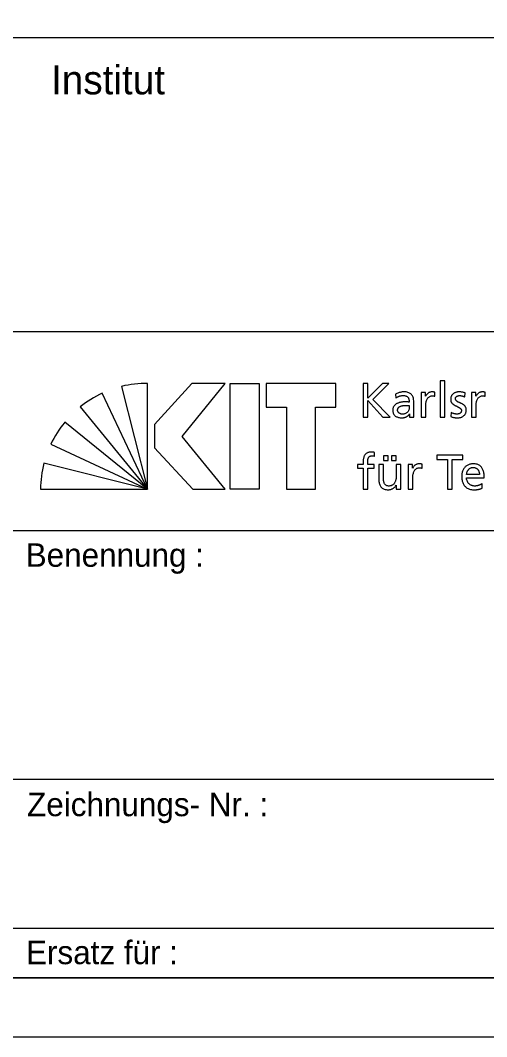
# Model space of a CAD drawing. Extents: x 0 to 21, y 0 to 14.9.
# Drawn here: x 18.816 to 19.808, y 0 to 2.162 of the extents above; entities that cross this region are included whole.
import ezdxf

# ---------------------------------------------------------------- set-up
doc = ezdxf.new("R2010")
doc.units = 0
doc.layers.add('90_Plankopf', color=7, linetype='Continuous')

msp = doc.modelspace()

# ---------------------------------------------------------------- linework, layer by layer
at = {"layer": '90_Plankopf'}
for p, q in [((20.9, 2.1248), (16.453, 2.1248)), ((16.453, 1.4998), (20.9, 1.4998)), ((16.453, 1.4998), (20.9, 1.4998)), ((19.087, 1.1647), (19.087, 1.3896)), ((19.5452, 1.3897), (19.5452, 1.3176)), ((19.087, 1.1647), (18.9908, 1.3688)), ((19.0319, 1.3833), (19.087, 1.1647)), ((19.6145, 1.3665), (19.615, 1.3583)), ((19.6982, 1.3621), (19.6982, 1.3708)), ((19.7614, 1.361), (19.7622, 1.3694)), ((19.8053, 1.3621), (19.8053, 1.3708)), ((19.6433, 1.3427), (19.6433, 1.3381)), ((19.653, 1.328), (19.653, 1.3497)), ((18.9436, 1.3396), (19.087, 1.1647)), ((19.7324, 1.328), (19.7319, 1.3193)), ((19.087, 1.1647), (18.9108, 1.3071)), ((19.5452, 1.3176), (19.5556, 1.3176)), ((19.5876, 1.3176), (19.6027, 1.3176)), ((18.881, 1.2603), (19.087, 1.1647)), ((19.5693, 1.2348), (19.5697, 1.2427)), ((19.087, 1.1647), (18.8664, 1.2197)), ((19.6707, 1.2091), (19.6707, 1.2178)), ((19.7927, 1.196), (19.7654, 1.196)), ((19.7654, 1.1888), (19.803, 1.1888)), ((19.7989, 1.1668), (19.7989, 1.1765)), ((18.8591, 1.1647), (19.087, 1.1647)), ((18.8, 1.0768), (20.9, 1.0768)), ((18.8, 0.548), (20.9, 0.548)), ((18.8, 0.2308), (20.9, 0.2308)), ((20.9, 0.125), (16.453, 0.125)), ((16.745, 0.125), (20.9, 0.125)), ((16.745, 0.125), (20.9, 0.125))]:
    msp.add_line(p, q, dxfattribs=at)
for points in [[(0, 0), (21.025, 0), (21.025, 14.85), (0, 14.85)], [(0.625, 14.725), (20.9, 14.725), (20.9, 0.125), (0.625, 0.125)], [(19.2517, 1.3897), (19.1809, 1.3897), (19.1018, 1.3025), (19.1018, 1.2523), (19.1834, 1.1647), (19.2521, 1.1647), (19.1606, 1.2766)], [(19.3243, 1.3897), (19.3243, 1.1647), (19.2625, 1.1647), (19.2625, 1.3897)], [(19.3391, 1.3897), (19.3391, 1.339), (19.3825, 1.339), (19.3825, 1.1647), (19.4443, 1.1647), (19.4443, 1.339), (19.4877, 1.339), (19.4877, 1.3897)]]:
    msp.add_lwpolyline(points, close=True, dxfattribs=at)
for points in [[(19.6027, 1.3176), (19.5662, 1.3556), (19.6, 1.3897), (19.5863, 1.3897), (19.5556, 1.358), (19.5556, 1.3897), (19.5452, 1.3897)], [(19.7095, 1.3176), (19.7192, 1.3176), (19.7192, 1.395), (19.7095, 1.395), (19.7095, 1.3176)], [(19.678, 1.3621), (19.6778, 1.3621), (19.6778, 1.3703), (19.6688, 1.3703), (19.6688, 1.3176), (19.6785, 1.3176), (19.6785, 1.3416)], [(19.7852, 1.3621), (19.785, 1.3621), (19.785, 1.3703), (19.7759, 1.3703), (19.7759, 1.3176), (19.7856, 1.3176), (19.7856, 1.3416)], [(19.5556, 1.3176), (19.5556, 1.3529), (19.5876, 1.3176)], [(19.6441, 1.3245), (19.6443, 1.3245), (19.6443, 1.3176), (19.6534, 1.3176)], [(19.5889, 1.2356), (19.5889, 1.2253), (19.5986, 1.2253), (19.5986, 1.2356), (19.5889, 1.2356)], [(19.6058, 1.2356), (19.6058, 1.2253), (19.6155, 1.2253), (19.6155, 1.2356), (19.6058, 1.2356)], [(19.7248, 1.1647), (19.7351, 1.1647), (19.7351, 1.2276), (19.7575, 1.2276), (19.7575, 1.2367), (19.7024, 1.2367), (19.7024, 1.2276), (19.7248, 1.2276), (19.7248, 1.1647)], [(19.5456, 1.2221), (19.5456, 1.2173), (19.5332, 1.2173), (19.5332, 1.2094), (19.5456, 1.2094), (19.5456, 1.1647), (19.5553, 1.1647), (19.5553, 1.2094), (19.5692, 1.2094), (19.5692, 1.2173), (19.5553, 1.2173), (19.5553, 1.223)], [(19.5885, 1.19), (19.5885, 1.2173), (19.5788, 1.2173), (19.5788, 1.186)], [(19.6254, 1.1647), (19.6254, 1.2173), (19.6157, 1.2173), (19.6157, 1.1929)], [(19.6506, 1.2091), (19.6504, 1.2091), (19.6504, 1.2173), (19.6413, 1.2173), (19.6413, 1.1647), (19.651, 1.1647), (19.651, 1.1886)], [(19.6158, 1.173), (19.616, 1.173), (19.616, 1.1647), (19.6254, 1.1647)]]:
    msp.add_lwpolyline(points, dxfattribs=at)
for centre, start, end in [((19.0862, 1.1514), 89.8053, 103.1895), ((19.0915, 1.1529), 115.0126, 128.3968), ((19.0954, 1.1566), 140.7898, 154.174), ((19.0973, 1.1609), 165.7222, 179.1064)]:
    msp.add_arc(centre, 0.2382, start, end, dxfattribs=at)
for points in [[(19.653, 1.3497), (19.653, 1.3545), (19.6523, 1.3585), (19.6508, 1.3617), (19.6494, 1.365), (19.6471, 1.3674), (19.644, 1.369), (19.6409, 1.3707), (19.6368, 1.3715), (19.6318, 1.3715), (19.6285, 1.3715), (19.6253, 1.371), (19.6224, 1.3701), (19.6195, 1.3692), (19.6169, 1.368), (19.6145, 1.3665)], [(19.615, 1.3583), (19.6163, 1.3594), (19.6178, 1.3604), (19.6195, 1.3611), (19.6211, 1.362), (19.6229, 1.3626), (19.6247, 1.363), (19.6266, 1.3634), (19.6284, 1.3637), (19.6303, 1.3637), (19.6335, 1.3637), (19.636, 1.3631), (19.6379, 1.3621), (19.6399, 1.3611), (19.6412, 1.3596), (19.642, 1.3575), (19.6429, 1.3555), (19.6433, 1.353), (19.6433, 1.3499)], [(19.6982, 1.3708), (19.6975, 1.3709), (19.6968, 1.371), (19.6962, 1.3712), (19.6956, 1.3713), (19.6949, 1.3713), (19.6942, 1.3714), (19.6935, 1.3715), (19.6927, 1.3715), (19.6918, 1.3715), (19.6899, 1.3715), (19.6881, 1.3711), (19.6863, 1.3703), (19.6845, 1.3695), (19.6829, 1.3684), (19.6815, 1.367), (19.6801, 1.3656), (19.6789, 1.3639), (19.678, 1.3621)], [(19.6785, 1.3416), (19.6785, 1.346), (19.6791, 1.3498), (19.6802, 1.353), (19.6814, 1.3562), (19.6831, 1.3587), (19.6852, 1.3604), (19.6874, 1.3621), (19.6899, 1.363), (19.6928, 1.363), (19.6936, 1.3631), (19.6945, 1.363), (19.6954, 1.3629), (19.6964, 1.3627), (19.6973, 1.3625), (19.6982, 1.3621)], [(19.7622, 1.3694), (19.7604, 1.37), (19.7584, 1.3705), (19.7565, 1.3709), (19.7545, 1.3713), (19.7524, 1.3715), (19.7502, 1.3715), (19.7476, 1.3715), (19.7451, 1.3712), (19.7429, 1.3705), (19.7406, 1.3698), (19.7387, 1.3688), (19.737, 1.3675), (19.7353, 1.3662), (19.734, 1.3645), (19.733, 1.3625), (19.7321, 1.3604), (19.7316, 1.358), (19.7316, 1.3553), (19.7316, 1.3532), (19.7321, 1.3514), (19.7329, 1.3498), (19.7337, 1.3483), (19.7348, 1.347), (19.7361, 1.3459), (19.7375, 1.3447), (19.739, 1.3437), (19.7406, 1.3429), (19.7422, 1.342), (19.7438, 1.3412), (19.7454, 1.3404), (19.7471, 1.3397), (19.7485, 1.3389), (19.7499, 1.338), (19.7512, 1.3373), (19.7523, 1.3363), (19.7532, 1.3353), (19.754, 1.3343), (19.7544, 1.3331), (19.7544, 1.3318), (19.7544, 1.3304), (19.7541, 1.3292), (19.7535, 1.3282), (19.7529, 1.3272), (19.7521, 1.3265), (19.7511, 1.3259), (19.7501, 1.3253), (19.7491, 1.3249), (19.7479, 1.3246), (19.7468, 1.3244), (19.7456, 1.3242), (19.7445, 1.3242), (19.7435, 1.3242), (19.7424, 1.3244), (19.741, 1.3247), (19.7396, 1.3249), (19.7381, 1.3253), (19.7366, 1.3259), (19.7351, 1.3265), (19.7337, 1.3271), (19.7324, 1.328)], [(19.7319, 1.3193), (19.7342, 1.3181), (19.7365, 1.3174), (19.7389, 1.317), (19.7414, 1.3166), (19.7439, 1.3164), (19.7464, 1.3164), (19.7487, 1.3164), (19.751, 1.3167), (19.7532, 1.3174), (19.7554, 1.318), (19.7573, 1.3191), (19.7591, 1.3204), (19.7608, 1.3217), (19.7622, 1.3234), (19.7632, 1.3255), (19.7642, 1.3276), (19.7647, 1.33), (19.7647, 1.3328), (19.7647, 1.3352), (19.7643, 1.3372), (19.7635, 1.3389), (19.7626, 1.3406), (19.7616, 1.342), (19.7602, 1.3431), (19.7589, 1.3443), (19.7574, 1.3453), (19.7557, 1.3461), (19.7541, 1.3469), (19.7525, 1.3477), (19.7509, 1.3484), (19.7493, 1.3491), (19.7478, 1.3499), (19.7464, 1.3507), (19.7451, 1.3515), (19.744, 1.3524), (19.7432, 1.3534), (19.7424, 1.3545), (19.7419, 1.3557), (19.7419, 1.3573), (19.7419, 1.3587), (19.7424, 1.3599), (19.7432, 1.3609), (19.7441, 1.3618), (19.7452, 1.3625), (19.7466, 1.363), (19.748, 1.3634), (19.7495, 1.3637), (19.7512, 1.3637), (19.7518, 1.3637), (19.7526, 1.3636), (19.7535, 1.3634), (19.7544, 1.3633), (19.7553, 1.3631), (19.7564, 1.3628), (19.7574, 1.3626), (19.7583, 1.3623), (19.7592, 1.362), (19.7601, 1.3616), (19.7609, 1.3613), (19.7614, 1.361)], [(19.8053, 1.3708), (19.8046, 1.3709), (19.804, 1.371), (19.8034, 1.3712), (19.8027, 1.3713), (19.8021, 1.3713), (19.8014, 1.3714), (19.8007, 1.3715), (19.7998, 1.3715), (19.7989, 1.3715), (19.797, 1.3715), (19.7952, 1.3711), (19.7934, 1.3703), (19.7917, 1.3695), (19.7901, 1.3684), (19.7886, 1.367), (19.7872, 1.3656), (19.786, 1.3639), (19.7852, 1.3621)], [(19.7856, 1.3416), (19.7856, 1.346), (19.7862, 1.3498), (19.7874, 1.353), (19.7886, 1.3562), (19.7902, 1.3587), (19.7923, 1.3604), (19.7945, 1.3621), (19.797, 1.363), (19.7999, 1.363), (19.8008, 1.3631), (19.8016, 1.363), (19.8026, 1.3629), (19.8035, 1.3627), (19.8044, 1.3625), (19.8053, 1.3621)], [(19.6433, 1.3499), (19.642, 1.35), (19.6408, 1.3501), (19.6397, 1.3501), (19.6386, 1.3501), (19.6376, 1.3501), (19.6365, 1.3501), (19.6354, 1.3501), (19.6342, 1.3501), (19.6329, 1.3501), (19.6309, 1.3501), (19.6288, 1.35), (19.6266, 1.3496), (19.6243, 1.3492), (19.6221, 1.3487), (19.62, 1.3478), (19.6179, 1.347), (19.616, 1.346), (19.6142, 1.3446), (19.6125, 1.3433), (19.6111, 1.3416), (19.6101, 1.3397), (19.609, 1.3377), (19.6085, 1.3354), (19.6085, 1.3328), (19.6085, 1.329), (19.6094, 1.3259), (19.611, 1.3235), (19.6126, 1.3211), (19.6149, 1.3193), (19.6177, 1.3181), (19.6206, 1.317), (19.624, 1.3164), (19.6278, 1.3164), (19.63, 1.3164), (19.632, 1.3167), (19.6338, 1.3172), (19.6355, 1.3177), (19.6371, 1.3184), (19.6384, 1.3192), (19.6398, 1.32), (19.6409, 1.3209), (19.6418, 1.3218), (19.6428, 1.3228), (19.6435, 1.3236), (19.6441, 1.3245)], [(19.6433, 1.3381), (19.6433, 1.3354), (19.6427, 1.3331), (19.6416, 1.331), (19.6405, 1.3289), (19.6388, 1.3273), (19.6367, 1.3261), (19.6345, 1.3249), (19.6318, 1.3243), (19.6286, 1.3242), (19.6275, 1.3242), (19.6264, 1.3244), (19.6252, 1.3248), (19.6241, 1.3252), (19.623, 1.3257), (19.622, 1.3264), (19.6211, 1.3272), (19.6203, 1.3281), (19.6197, 1.3291), (19.6191, 1.3302), (19.6188, 1.3314), (19.6188, 1.3328), (19.6188, 1.3347), (19.6193, 1.3362), (19.6202, 1.3374), (19.6211, 1.3387), (19.6223, 1.3396), (19.6237, 1.3404), (19.6252, 1.3411), (19.6267, 1.3417), (19.6284, 1.342), (19.63, 1.3424), (19.6316, 1.3426), (19.6332, 1.3428), (19.6347, 1.3429), (19.636, 1.3429), (19.6371, 1.3429), (19.6381, 1.3429), (19.6391, 1.3429), (19.6402, 1.3428), (19.6412, 1.3428), (19.6422, 1.3427), (19.6433, 1.3427)], [(19.6534, 1.3176), (19.6533, 1.3181), (19.6532, 1.3188), (19.6532, 1.3197), (19.6531, 1.3205), (19.6531, 1.3216), (19.653, 1.323), (19.653, 1.3243), (19.653, 1.326), (19.653, 1.328)], [(19.5697, 1.2427), (19.5688, 1.2428), (19.5678, 1.243), (19.5667, 1.2431), (19.5656, 1.2432), (19.5645, 1.2433), (19.5632, 1.2433), (19.5597, 1.2433), (19.5568, 1.2428), (19.5544, 1.2418), (19.5521, 1.2408), (19.5503, 1.2394), (19.5491, 1.2375), (19.5478, 1.2356), (19.5469, 1.2334), (19.5464, 1.2308), (19.5458, 1.2282), (19.5456, 1.2253), (19.5456, 1.2221)], [(19.5553, 1.223), (19.5553, 1.2247), (19.5554, 1.2264), (19.5556, 1.2279), (19.5558, 1.2294), (19.5562, 1.2307), (19.5569, 1.2319), (19.5575, 1.233), (19.5585, 1.2339), (19.5597, 1.2345), (19.561, 1.2351), (19.5626, 1.2354), (19.5647, 1.2354), (19.5655, 1.2354), (19.5664, 1.2354), (19.5672, 1.2353), (19.568, 1.2352), (19.5688, 1.235), (19.5693, 1.2348)], [(19.6707, 1.2178), (19.67, 1.2179), (19.6693, 1.2181), (19.6688, 1.2182), (19.6681, 1.2183), (19.6675, 1.2184), (19.6667, 1.2184), (19.6661, 1.2185), (19.6652, 1.2185), (19.6643, 1.2185), (19.6624, 1.2185), (19.6606, 1.2181), (19.6588, 1.2173), (19.6571, 1.2165), (19.6555, 1.2154), (19.654, 1.214), (19.6526, 1.2126), (19.6514, 1.211), (19.6506, 1.2091)], [(19.803, 1.1888), (19.803, 1.1931), (19.8026, 1.197), (19.8018, 1.2006), (19.801, 1.2042), (19.7997, 1.2073), (19.7979, 1.21), (19.7961, 1.2127), (19.7938, 1.2148), (19.7908, 1.2162), (19.7878, 1.2177), (19.7841, 1.2185), (19.7797, 1.2185), (19.776, 1.2185), (19.7726, 1.2178), (19.7696, 1.2166), (19.7666, 1.2152), (19.764, 1.2134), (19.7618, 1.2111), (19.7597, 1.2087), (19.758, 1.2059), (19.7569, 1.2026), (19.7557, 1.1994), (19.7551, 1.1958), (19.7551, 1.1919), (19.7551, 1.1876), (19.7556, 1.1837), (19.7567, 1.1802), (19.7578, 1.1767), (19.7595, 1.1737), (19.7617, 1.1712), (19.7639, 1.1687), (19.7668, 1.1668), (19.7702, 1.1655), (19.7736, 1.1641), (19.7777, 1.1634), (19.7823, 1.1634), (19.7852, 1.1634), (19.7876, 1.1636), (19.7897, 1.164), (19.7917, 1.1644), (19.7934, 1.1648), (19.7949, 1.1653), (19.7964, 1.1659), (19.7977, 1.1664), (19.7989, 1.1668)], [(19.7654, 1.196), (19.7656, 1.1977), (19.766, 1.1995), (19.7666, 1.2012), (19.7672, 1.2029), (19.7681, 1.2045), (19.7692, 1.2059), (19.7703, 1.2073), (19.7717, 1.2085), (19.7734, 1.2093), (19.7751, 1.2102), (19.7772, 1.2107), (19.7795, 1.2107), (19.7816, 1.2107), (19.7835, 1.2103), (19.7851, 1.2095), (19.7867, 1.2088), (19.7881, 1.2077), (19.7892, 1.2064), (19.7903, 1.205), (19.7912, 1.2035), (19.7918, 1.2017), (19.7924, 1.1999), (19.7927, 1.1981), (19.7927, 1.196)], [(19.6157, 1.1929), (19.6157, 1.1897), (19.6154, 1.1868), (19.6147, 1.1841), (19.6141, 1.1815), (19.6131, 1.1792), (19.6118, 1.1773), (19.6105, 1.1754), (19.6088, 1.1739), (19.6068, 1.1728), (19.6048, 1.1718), (19.6024, 1.1713), (19.5997, 1.1713), (19.5969, 1.1714), (19.5947, 1.1722), (19.593, 1.1736), (19.5914, 1.175), (19.5902, 1.1771), (19.5895, 1.1798), (19.5889, 1.1825), (19.5885, 1.1859), (19.5885, 1.19)], [(19.651, 1.1886), (19.651, 1.193), (19.6516, 1.1968), (19.6528, 1.2), (19.6539, 1.2032), (19.6556, 1.2057), (19.6577, 1.2074), (19.6599, 1.2092), (19.6624, 1.21), (19.6653, 1.21), (19.6662, 1.2101), (19.667, 1.21), (19.668, 1.2099), (19.6689, 1.2097), (19.6698, 1.2095), (19.6707, 1.2091)], [(19.5788, 1.186), (19.5788, 1.1813), (19.5795, 1.1772), (19.5809, 1.1739), (19.5823, 1.1705), (19.5845, 1.1679), (19.5874, 1.1661), (19.5903, 1.1644), (19.594, 1.1634), (19.5986, 1.1634), (19.601, 1.1634), (19.6034, 1.1638), (19.6056, 1.1646), (19.6079, 1.1653), (19.6099, 1.1665), (19.6117, 1.1679), (19.6134, 1.1693), (19.6148, 1.171), (19.6158, 1.173)], [(19.7989, 1.1765), (19.7983, 1.176), (19.7975, 1.1755), (19.7963, 1.1749), (19.7952, 1.1743), (19.7939, 1.1737), (19.7924, 1.1732), (19.7909, 1.1726), (19.7893, 1.1722), (19.7876, 1.1718), (19.786, 1.1715), (19.7844, 1.1713), (19.7827, 1.1713), (19.7804, 1.1713), (19.7782, 1.1717), (19.7762, 1.1725), (19.7741, 1.1734), (19.7722, 1.1746), (19.7706, 1.1761), (19.769, 1.1777), (19.7677, 1.1795), (19.7668, 1.1817), (19.7659, 1.1838), (19.7654, 1.1862), (19.7654, 1.1888)]]:
    msp.add_open_spline(points, degree=3, dxfattribs=at)

# ---------------------------------------------------------------- texts
for s, height, p in [('Institut', 0.0616, (18.8816, 2.0044)), ('Benennung :', 0.05, (18.8278, 0.9995)), ('Zeichnungs- Nr. :', 0.05, (18.8307, 0.469)), ('Ersatz für :', 0.05, (18.8285, 0.1542))]:
    msp.add_text(s, height=height, dxfattribs=at).set_placement(p)

doc.saveas('drawing.dxf')
